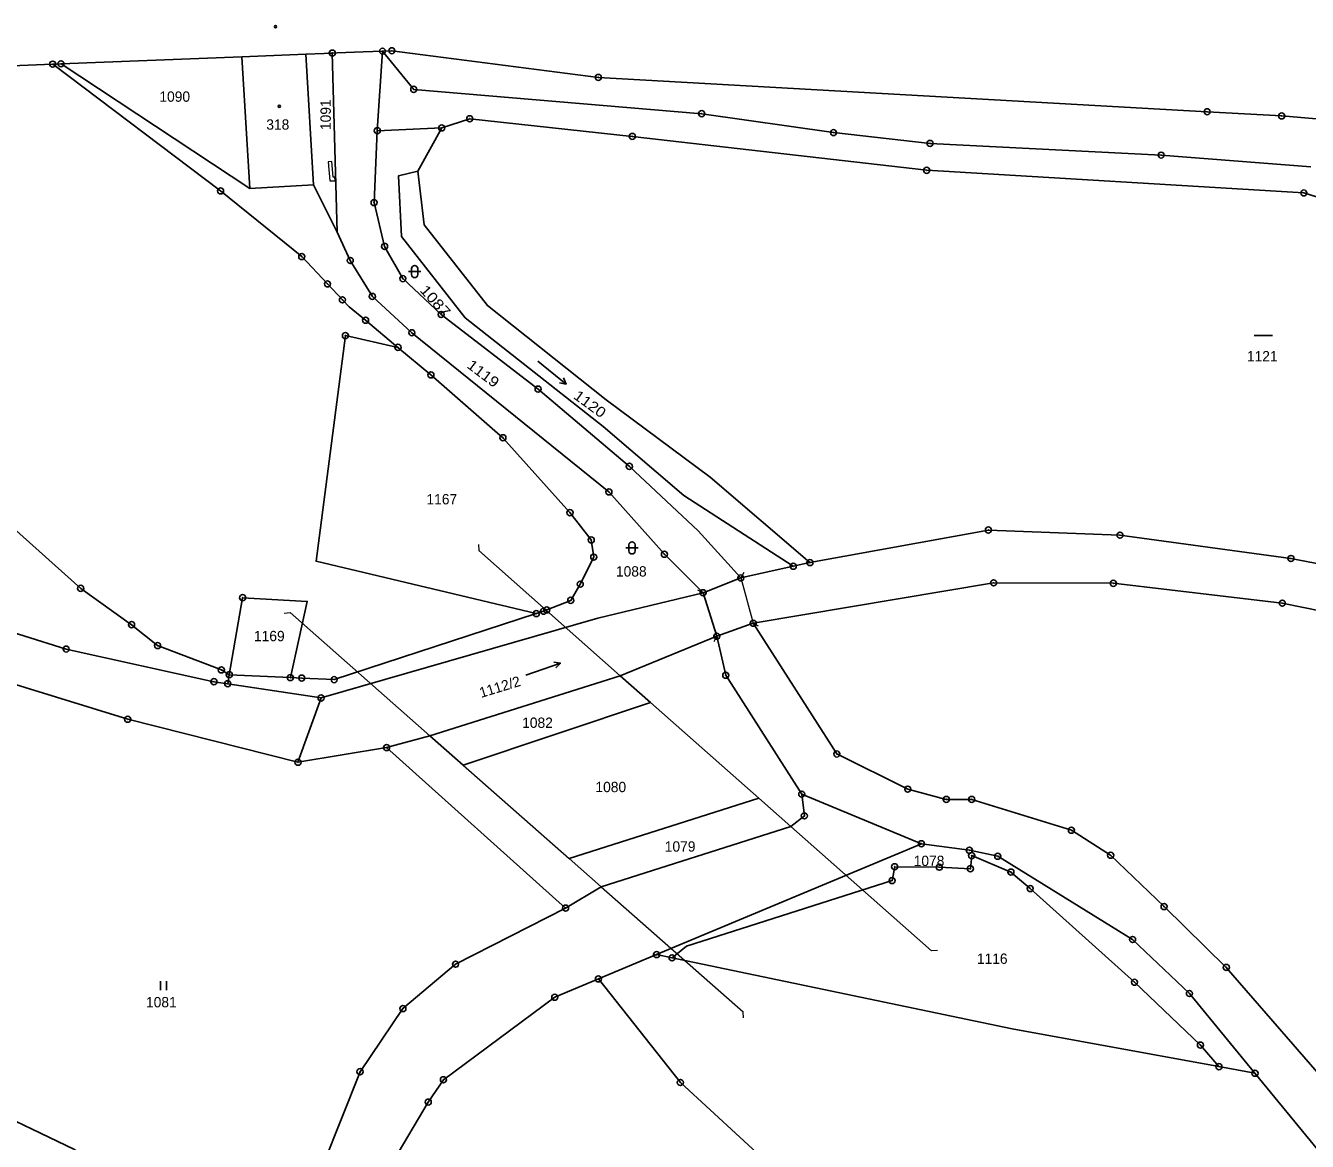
# Model space of a CAD drawing. Extents: x -758887 to -754328, y -1031688 to -1029144.
# Drawn here: x -758435 to -758223.9, y -1029327.6 to -1029143.8 of the extents above; entities that cross this region are included whole.
import ezdxf
from ezdxf.enums import TextEntityAlignment as Align

# ---------------------------------------------------------------- set-up
doc = ezdxf.new("R2010")
doc.units = 0
doc.header["$LTSCALE"] = 0.68
for name, color, linetype, lineweight in [('1', 7, 'Continuous', 25), ('13', 7, 'Continuous', 13), ('3', 7, 'Continuous', 25), ('4', 7, 'Continuous', 13), ('5', 7, 'Continuous', 25), ('8', 7, 'Continuous', 25)]:
    doc.layers.add(name, color=color, linetype=linetype, lineweight=lineweight)
doc.layers.add('2', color=7, linetype='Continuous')

msp = doc.modelspace()

# ---------------------------------------------------------------- linework, layer by layer
at = {"layer": '1'}
for p, q in [((-758429.19, -1029150.13), (-758399.41, -1029148.95)), ((-758399.41, -1029148.95), (-758388.86, -1029148.53)), ((-758388.86, -1029148.53), (-758385.84, -1029148.42)), ((-758387.59, -1029170.04), (-758388.86, -1029148.53)), ((-758385.84, -1029148.42), (-758385.18, -1029148.39)), ((-758385.18, -1029148.39), (-758384.52, -1029148.36)), ((-758384.52, -1029148.36), (-758383.68, -1029148.33)), ((-758383.69, -1029177.86), (-758384.52, -1029148.36)), ((-758377.11, -1029161.14), (-758376.24, -1029148.04)), ((-758376.24, -1029148.04), (-758374.7, -1029147.98)), ((-758430.56, -1029150.18), (-758429.19, -1029150.13)), ((-758398.07, -1029170.69), (-758429.19, -1029150.13)), ((-758383.69, -1029177.86), (-758387.59, -1029170.04)), ((-758308.58, -1029232.9), (-758305.84, -1029232.29)), ((-758323.44, -1029237.26), (-758321.17, -1029244.43)), ((-758315.18, -1029242.29), (-758321.17, -1029244.43)), ((-758321.17, -1029244.43), (-758337.07, -1029250.93)), ((-758391.41, -1029251.24), (-758401.47, -1029250.78)), ((-758337.07, -1029250.93), (-758368.43, -1029260.83)), ((-758337.07, -1029250.93), (-758332.09, -1029255.33)), ((-758390.16, -1029265.19), (-758386.36, -1029254.6)), ((-758368.43, -1029260.83), (-758375.57, -1029262.78)), ((-758375.57, -1029262.78), (-758390.16, -1029265.19)), ((-758307.18, -1029270.45), (-758287.47, -1029278.61)), ((-758331.09, -1029296.88), (-758340.67, -1029300.89))]:
    msp.add_line(p, q, dxfattribs=at)
for points in [[(-758399.41, -1029148.95), (-758398.07, -1029170.69), (-758387.59, -1029170.04)], [(-758383.68, -1029148.33), (-758379.42, -1029148.16), (-758376.24, -1029148.04)], [(-758376.24, -1029148.04), (-758371.09, -1029154.33), (-758323.67, -1029158.34), (-758301.96, -1029161.46), (-758286.05, -1029163.24), (-758247.99, -1029165.17), (-758223.33, -1029167.07)], [(-758374.7, -1029147.98), (-758340.67, -1029152.37), (-758240.41, -1029158.02)], [(-758519.87, -1029156.38), (-758490.37, -1029153.89), (-758473.85, -1029152.5), (-758472.04, -1029152.35), (-758460.36, -1029151.36), (-758456.33, -1029151.2), (-758430.56, -1029150.18)], [(-758430.56, -1029150.18), (-758402.9, -1029171.06), (-758389.54, -1029181.89), (-758385.3, -1029186.39), (-758382.84, -1029189.01), (-758381.73, -1029190.18), (-758379.02, -1029192.38), (-758373.69, -1029196.84)], [(-758240.41, -1029158.02), (-758228.14, -1029158.71), (-758184.57, -1029162.5), (-758098.34, -1029176.6), (-758087.31, -1029177.87)], [(-758116.76, -1029196.06), (-758146.77, -1029190.01), (-758200.54, -1029178.97), (-758224.49, -1029171.39), (-758286.61, -1029167.67), (-758335.09, -1029162.08), (-758361.87, -1029159.17), (-758366.48, -1029160.68)], [(-758377.11, -1029161.14), (-758377.63, -1029172.99), (-758375.9, -1029180.21), (-758372.89, -1029185.52), (-758366.58, -1029191.42), (-758350.62, -1029203.72), (-758335.58, -1029216.44), (-758324.24, -1029227.07), (-758317.22, -1029234.82)], [(-758370.44, -1029167.83), (-758366.48, -1029160.68), (-758377.11, -1029161.14)], [(-758308.58, -1029232.9), (-758326.61, -1029221.24), (-758339.91, -1029209.85), (-758362.61, -1029191.98), (-758373.12, -1029178.58), (-758373.63, -1029168.59), (-758370.44, -1029167.83)], [(-758305.84, -1029232.29), (-758322.28, -1029218.25), (-758339.42, -1029205.48), (-758358.95, -1029189.96), (-758369.35, -1029176.63), (-758370.44, -1029167.83)], [(-758323.44, -1029237.26), (-758329.81, -1029230.93), (-758338.94, -1029220.66), (-758371.41, -1029194.43), (-758377.91, -1029188.45), (-758381.55, -1029182.53), (-758383.69, -1029177.86)], [(-758401.47, -1029250.78), (-758402.78, -1029249.98), (-758413.29, -1029245.97), (-758417.57, -1029242.53), (-758425.95, -1029236.54), (-758437, -1029226.65), (-758467.17, -1029201.22), (-758490.33, -1029182.16)], [(-758821.62, -1029188.2), (-758803.54, -1029192.38), (-758764.19, -1029202.23), (-758728.57, -1029211.45), (-758684.41, -1029222.59), (-758639.98, -1029230.68), (-758608.27, -1029234.2), (-758578.65, -1029235.81), (-758561.56, -1029238.41), (-758526.08, -1029238.52), (-758490.44, -1029236.79), (-758465.04, -1029235.05), (-758428.34, -1029246.54), (-758404, -1029251.92), (-758401.73, -1029252.26)], [(-758373.69, -1029196.84), (-758382.34, -1029194.9), (-758387.19, -1029232.09), (-758350.92, -1029240.7)], [(-758373.69, -1029196.84), (-758368.27, -1029201.38), (-758356.4, -1029211.73), (-758345.36, -1029224.07), (-758341.85, -1029228.57), (-758341.44, -1029231.4), (-758343.67, -1029235.85), (-758345.24, -1029238.52), (-758349.18, -1029240.09), (-758349.72, -1029240.31), (-758350.92, -1029240.7)], [(-758305.84, -1029232.29), (-758276.44, -1029226.93), (-758254.79, -1029227.78), (-758226.62, -1029231.62), (-758183.35, -1029239.91), (-758120.85, -1029256.32)], [(-758323.44, -1029237.26), (-758317.22, -1029234.82), (-758308.58, -1029232.9)], [(-757986.46, -1029302.93), (-758014.95, -1029292.13), (-758063.96, -1029279.67), (-758122.9, -1029264.06), (-758185.39, -1029247.65), (-758228.04, -1029238.98), (-758255.87, -1029235.71), (-758275.59, -1029235.63), (-758315.18, -1029242.29)], [(-758401.47, -1029250.78), (-758399.28, -1029238.08), (-758388.64, -1029238.69), (-758391.41, -1029251.24)], [(-758386.36, -1029254.6), (-758340.79, -1029241.46), (-758323.44, -1029237.26)], [(-758350.92, -1029240.7), (-758384.2, -1029251.58), (-758389.53, -1029251.33), (-758391.41, -1029251.24)], [(-758214.63, -1029325.07), (-758237.26, -1029298.99), (-758247.51, -1029288.97), (-758256.31, -1029280.52), (-758262.77, -1029276.4), (-758279.18, -1029271.31), (-758283.38, -1029271.32), (-758289.72, -1029269.62), (-758301.41, -1029263.83), (-758315.18, -1029242.29)], [(-758307.18, -1029270.45), (-758319.71, -1029250.86), (-758321.17, -1029244.43)], [(-758390.16, -1029265.19), (-758418.21, -1029258.11), (-758446.92, -1029249.26), (-758453.37, -1029246.98)], [(-758401.47, -1029250.78), (-758401.73, -1029252.26), (-758386.36, -1029254.6)], [(-758332.09, -1029255.33), (-758362.95, -1029265.65), (-758368.43, -1029260.83)], [(-758375.57, -1029262.78), (-758346.08, -1029289.22), (-758340.22, -1029285.69)], [(-758309.01, -1029275.75), (-758306.76, -1029274.02), (-758307.18, -1029270.45)], [(-758287.47, -1029278.61), (-758331.09, -1029296.88), (-758328.55, -1029297.41)], [(-758232.54, -1029316.42), (-758243.34, -1029303.29), (-758252.7, -1029294.39), (-758274.91, -1029280.68), (-758279.57, -1029279.69), (-758287.47, -1029278.61)], [(-758328.55, -1029297.41), (-758326.19, -1029295.49), (-758292.3, -1029284.68), (-758291.88, -1029282.41), (-758284.54, -1029282.48), (-758279.41, -1029282.73), (-758279.2, -1029280.56), (-758272.73, -1029283.29), (-758269.56, -1029286.01), (-758252.38, -1029301.44), (-758241.53, -1029311.79), (-758238.47, -1029315.34), (-758232.54, -1029316.42)], [(-758392.05, -1029348.07), (-758389, -1029338.93), (-758379.94, -1029316.17), (-758372.88, -1029305.78), (-758364.21, -1029298.46), (-758346.08, -1029289.22)], [(-758238.47, -1029315.34), (-758272.52, -1029309.13), (-758328.55, -1029297.41)], [(-758340.67, -1029300.89), (-758347.87, -1029303.9), (-758366.2, -1029317.5), (-758368.71, -1029321.17), (-758374.39, -1029330.73), (-758378.89, -1029344.86), (-758384.41, -1029360.14), (-758394.64, -1029390.44), (-758399.55, -1029401.61), (-758407.78, -1029412.68), (-758420.82, -1029419.96), (-758434.38, -1029424.1)], [(-758190.92, -1029431.64), (-758198.56, -1029424.31), (-758240.61, -1029385.61), (-758265.6, -1029364.46), (-758297.96, -1029342.37), (-758312.48, -1029331.46), (-758327.18, -1029317.95), (-758340.67, -1029300.89)], [(-758454.59, -1029315.76), (-758427.08, -1029328.92), (-758412.67, -1029338.97), (-758404.39, -1029347.29), (-758392.05, -1029348.07)], [(-758132.9, -1029435.24), (-758143.97, -1029427.02), (-758147.78, -1029422.95), (-758152.98, -1029416.21), (-758166.32, -1029397.91), (-758201.41, -1029354.28), (-758232.54, -1029316.42)]]:
    msp.add_lwpolyline(points, dxfattribs=at)
msp.add_lwpolyline([(-758340.22, -1029285.69), (-758309.01, -1029275.75), (-758314.23, -1029271.13), (-758345.49, -1029281.04)], close=True, dxfattribs=at)
at = {"layer": '13'}
msp.add_lwpolyline([(-758384.06, -1029169.39), (-758384.07, -1029168.79), (-758384.37, -1029168.79), (-758384.61, -1029166.21), (-758385.21, -1029166.27), (-758384.91, -1029169.39)], close=True, dxfattribs=at)
at = {"layer": '3'}
for p, q in [((-758371.941, -1029184.351), (-758369.939, -1029184.351)), ((-758371.441, -1029183.851), (-758371.441, -1029184.852)), ((-758370.439, -1029184.852), (-758370.439, -1029183.851)), ((-758232.668, -1029194.86), (-758229.668, -1029194.86)), ((-758345.991, -1029202.885), (-758347.066, -1029202.66)), ((-758336.141, -1029229.871), (-758334.139, -1029229.871)), ((-758335.641, -1029229.371), (-758335.641, -1029230.372)), ((-758334.639, -1029230.372), (-758334.639, -1029229.371)), ((-758346.934, -1029248.866), (-758347.695, -1029249.658)), ((-758412.801, -1029302.75), (-758412.801, -1029301.25)), ((-758411.8, -1029302.75), (-758411.8, -1029301.25))]:
    msp.add_line(p, q, dxfattribs=at)
for points in [[(-758350.654, -1029199.109), (-758345.991, -1029202.885), (-758346.434, -1029201.881)], [(-758352.608, -1029250.819), (-758346.934, -1029248.866), (-758348.022, -1029248.71)]]:
    msp.add_lwpolyline(points, dxfattribs=at)
for centre, start, end in [((-758370.94, -1029183.8509), 0, 180), ((-758370.94, -1029184.8509), 180, 359.98789), ((-758335.14, -1029229.3709), 0, 180), ((-758335.14, -1029230.3709), 180, 359.98789)]:
    msp.add_arc(centre, 0.5, start, end, dxfattribs=at)
at = {"layer": '4'}
for p, q in [((-758360.442, -1029229.301), (-758360.389, -1029230.299)), ((-758360.39, -1029230.3), (-758337.07, -1029250.93)), ((-758316.719, -1029233.954), (-758317.219, -1029234.82)), ((-758317.22, -1029234.82), (-758315.18, -1029242.29)), ((-758324.331, -1029236.805), (-758323.44, -1029237.259)), ((-758392.448, -1029240.609), (-758391.451, -1029240.539)), ((-758391.45, -1029240.54), (-758368.43, -1029260.83)), ((-758314.314, -1029242.791), (-758315.18, -1029242.291)), ((-758321.625, -1029245.321), (-758321.171, -1029244.43)), ((-758332.09, -1029255.33), (-758314.23, -1029271.13)), ((-758362.95, -1029265.65), (-758345.49, -1029281.04)), ((-758309.01, -1029275.75), (-758285.83, -1029296.25)), ((-758340.22, -1029285.69), (-758316.84, -1029306.29)), ((-758284.831, -1029296.198), (-758285.829, -1029296.251)), ((-758316.771, -1029307.288), (-758316.841, -1029306.291))]:
    msp.add_line(p, q, dxfattribs=at)
at = {"layer": '5'}
for centre in [(-758393.8568, -1029144.0092), (-758393.2368, -1029157.1392)]:
    msp.add_circle(centre, 0.175, dxfattribs=at)
at = {"layer": '8'}
for centre, radius in [((-758384.52, -1029148.3599), 0.5), ((-758376.24, -1029148.0399), 0.5), ((-758374.7, -1029147.9799), 0.5), ((-758430.56, -1029150.1799), 0.5), ((-758429.19, -1029150.1299), 0.5), ((-758384.52, -1029148.3599), 0.0303), ((-758376.24, -1029148.0399), 0.0303), ((-758374.7, -1029147.9799), 0.0303), ((-758430.56, -1029150.1799), 0.0303), ((-758429.19, -1029150.1299), 0.0303), ((-758340.67, -1029152.3699), 0.5), ((-758371.09, -1029154.3299), 0.5), ((-758340.67, -1029152.3699), 0.0303), ((-758371.09, -1029154.3299), 0.0303), ((-758323.67, -1029158.3399), 0.5), ((-758323.67, -1029158.3399), 0.0303), ((-758240.41, -1029158.0199), 0.5), ((-758240.41, -1029158.0199), 0.0303), ((-758228.14, -1029158.7099), 0.5), ((-758366.48, -1029160.6799), 0.5), ((-758361.87, -1029159.1699), 0.5), ((-758361.87, -1029159.1699), 0.0303), ((-758228.14, -1029158.7099), 0.0303), ((-758377.11, -1029161.1399), 0.5), ((-758377.11, -1029161.1399), 0.0303), ((-758366.48, -1029160.6799), 0.0303), ((-758335.09, -1029162.0799), 0.5), ((-758335.09, -1029162.0799), 0.0303), ((-758301.96, -1029161.4599), 0.5), ((-758301.96, -1029161.4599), 0.0303), ((-758286.05, -1029163.2399), 0.5), ((-758286.05, -1029163.2399), 0.0303), ((-758247.99, -1029165.1699), 0.5), ((-758247.99, -1029165.1699), 0.0303), ((-758286.61, -1029167.6699), 0.5), ((-758286.61, -1029167.6699), 0.0303), ((-758402.9, -1029171.0599), 0.5), ((-758402.9, -1029171.0599), 0.0303), ((-758224.49, -1029171.3899), 0.5), ((-758377.63, -1029172.9899), 0.5), ((-758377.63, -1029172.9899), 0.0303), ((-758224.49, -1029171.3899), 0.0303), ((-758389.54, -1029181.8899), 0.5), ((-758375.9, -1029180.2099), 0.5), ((-758375.9, -1029180.2099), 0.0303), ((-758389.54, -1029181.8899), 0.0303), ((-758381.55, -1029182.5299), 0.5), ((-758381.55, -1029182.5299), 0.0303), ((-758385.3, -1029186.3899), 0.5), ((-758372.89, -1029185.5199), 0.5), ((-758372.89, -1029185.5199), 0.0303), ((-758385.3, -1029186.3899), 0.0303), ((-758377.91, -1029188.4499), 0.5), ((-758382.84, -1029189.0099), 0.5), ((-758382.84, -1029189.0099), 0.0303), ((-758377.91, -1029188.4499), 0.0303), ((-758379.02, -1029192.3799), 0.5), ((-758366.58, -1029191.4199), 0.5), ((-758366.58, -1029191.4199), 0.0303), ((-758379.02, -1029192.3799), 0.0303), ((-758371.41, -1029194.4299), 0.5), ((-758382.34, -1029194.8999), 0.5), ((-758382.34, -1029194.8999), 0.0303), ((-758373.69, -1029196.8399), 0.5), ((-758371.41, -1029194.4299), 0.0303), ((-758373.69, -1029196.8399), 0.0303), ((-758368.27, -1029201.3799), 0.5), ((-758368.27, -1029201.3799), 0.0303), ((-758350.62, -1029203.7199), 0.5), ((-758350.62, -1029203.7199), 0.0303), ((-758356.4, -1029211.7299), 0.5), ((-758356.4, -1029211.7299), 0.0303), ((-758335.58, -1029216.4399), 0.5), ((-758335.58, -1029216.4399), 0.0303), ((-758338.94, -1029220.6599), 0.5), ((-758338.94, -1029220.6599), 0.0303), ((-758345.36, -1029224.0699), 0.5), ((-758345.36, -1029224.0699), 0.0303), ((-758341.85, -1029228.5699), 0.5), ((-758276.44, -1029226.9299), 0.5), ((-758276.44, -1029226.9299), 0.0303), ((-758254.79, -1029227.7799), 0.5), ((-758254.79, -1029227.7799), 0.0303), ((-758341.85, -1029228.5699), 0.0303), ((-758341.44, -1029231.3999), 0.5), ((-758341.44, -1029231.3999), 0.0303), ((-758329.81, -1029230.9299), 0.5), ((-758329.81, -1029230.9299), 0.0303), ((-758305.84, -1029232.2899), 0.5), ((-758305.84, -1029232.2899), 0.0303), ((-758226.62, -1029231.6199), 0.5), ((-758226.62, -1029231.6199), 0.0303), ((-758317.22, -1029234.8199), 0.5), ((-758308.58, -1029232.8999), 0.5), ((-758308.58, -1029232.8999), 0.0303), ((-758425.95, -1029236.5399), 0.5), ((-758425.95, -1029236.5399), 0.0303), ((-758343.67, -1029235.8499), 0.5), ((-758343.67, -1029235.8499), 0.0303), ((-758317.22, -1029234.8199), 0.0303), ((-758275.59, -1029235.6299), 0.5), ((-758275.59, -1029235.6299), 0.0303), ((-758255.87, -1029235.7099), 0.5), ((-758255.87, -1029235.7099), 0.0303), ((-758399.28, -1029238.0799), 0.5), ((-758399.28, -1029238.0799), 0.0303), ((-758345.24, -1029238.5199), 0.5), ((-758345.24, -1029238.5199), 0.0303), ((-758323.44, -1029237.2599), 0.5), ((-758323.44, -1029237.2599), 0.0303), ((-758228.04, -1029238.9799), 0.5), ((-758350.92, -1029240.6999), 0.5), ((-758350.92, -1029240.6999), 0.0303), ((-758349.72, -1029240.3099), 0.5), ((-758349.72, -1029240.3099), 0.0303), ((-758349.18, -1029240.0899), 0.5), ((-758349.18, -1029240.0899), 0.0303), ((-758228.04, -1029238.9799), 0.0303), ((-758417.57, -1029242.5299), 0.5), ((-758417.57, -1029242.5299), 0.0303), ((-758315.18, -1029242.2899), 0.5), ((-758315.18, -1029242.2899), 0.0303), ((-758321.17, -1029244.4299), 0.5), ((-758321.17, -1029244.4299), 0.0303), ((-758428.34, -1029246.5399), 0.5), ((-758428.34, -1029246.5399), 0.0303), ((-758413.29, -1029245.9699), 0.5), ((-758413.29, -1029245.9699), 0.0303), ((-758402.78, -1029249.9799), 0.5), ((-758402.78, -1029249.9799), 0.0303), ((-758401.47, -1029250.7799), 0.5), ((-758401.47, -1029250.7799), 0.0303), ((-758391.41, -1029251.2399), 0.5), ((-758391.41, -1029251.2399), 0.0303), ((-758389.53, -1029251.3299), 0.5), ((-758389.53, -1029251.3299), 0.0303), ((-758384.2, -1029251.5799), 0.5), ((-758319.71, -1029250.8599), 0.5), ((-758319.71, -1029250.8599), 0.0303), ((-758404, -1029251.9199), 0.5), ((-758404, -1029251.9199), 0.0303), ((-758401.73, -1029252.2599), 0.5), ((-758401.73, -1029252.2599), 0.0303), ((-758384.2, -1029251.5799), 0.0303), ((-758386.36, -1029254.5999), 0.5), ((-758386.36, -1029254.5999), 0.0303), ((-758418.21, -1029258.1099), 0.5), ((-758418.21, -1029258.1099), 0.0303), ((-758375.57, -1029262.7799), 0.5), ((-758375.57, -1029262.7799), 0.0303), ((-758301.41, -1029263.8299), 0.5), ((-758301.41, -1029263.8299), 0.0303), ((-758390.16, -1029265.1899), 0.5), ((-758390.16, -1029265.1899), 0.0303), ((-758307.18, -1029270.4499), 0.5), ((-758289.72, -1029269.6199), 0.5), ((-758289.72, -1029269.6199), 0.0303), ((-758307.18, -1029270.4499), 0.0303), ((-758283.38, -1029271.3199), 0.5), ((-758283.38, -1029271.3199), 0.0303), ((-758279.18, -1029271.3099), 0.5), ((-758279.18, -1029271.3099), 0.0303), ((-758306.76, -1029274.0199), 0.5), ((-758306.76, -1029274.0199), 0.0303), ((-758262.77, -1029276.3999), 0.5), ((-758262.77, -1029276.3999), 0.0303), ((-758287.47, -1029278.6099), 0.5), ((-758287.47, -1029278.6099), 0.0303), ((-758279.57, -1029279.6899), 0.5), ((-758279.2, -1029280.5599), 0.5), ((-758279.57, -1029279.6899), 0.0303), ((-758279.2, -1029280.5599), 0.0303), ((-758274.91, -1029280.6799), 0.5), ((-758274.91, -1029280.6799), 0.0303), ((-758256.31, -1029280.5199), 0.5), ((-758256.31, -1029280.5199), 0.0303), ((-758291.88, -1029282.4099), 0.5), ((-758291.88, -1029282.4099), 0.0303), ((-758284.54, -1029282.4799), 0.5), ((-758284.54, -1029282.4799), 0.0303), ((-758279.41, -1029282.7299), 0.5), ((-758279.41, -1029282.7299), 0.0303), ((-758272.73, -1029283.2899), 0.5), ((-758292.3, -1029284.6799), 0.5), ((-758292.3, -1029284.6799), 0.0303), ((-758272.73, -1029283.2899), 0.0303), ((-758269.56, -1029286.0099), 0.5), ((-758269.56, -1029286.0099), 0.0303), ((-758346.08, -1029289.2199), 0.5), ((-758346.08, -1029289.2199), 0.0303), ((-758247.51, -1029288.9699), 0.5), ((-758247.51, -1029288.9699), 0.0303), ((-758252.7, -1029294.3899), 0.5), ((-758252.7, -1029294.3899), 0.0303), ((-758331.09, -1029296.8799), 0.5), ((-758331.09, -1029296.8799), 0.0303), ((-758328.55, -1029297.4099), 0.5), ((-758328.55, -1029297.4099), 0.0303), ((-758364.21, -1029298.4599), 0.5), ((-758364.21, -1029298.4599), 0.0303), ((-758237.26, -1029298.9899), 0.5), ((-758237.26, -1029298.9899), 0.0303), ((-758340.67, -1029300.8899), 0.5), ((-758340.67, -1029300.8899), 0.0303), ((-758252.38, -1029301.4399), 0.5), ((-758252.38, -1029301.4399), 0.0303), ((-758347.87, -1029303.8999), 0.5), ((-758347.87, -1029303.8999), 0.0303), ((-758243.34, -1029303.2899), 0.5), ((-758243.34, -1029303.2899), 0.0303), ((-758372.88, -1029305.7799), 0.5), ((-758372.88, -1029305.7799), 0.0303), ((-758241.53, -1029311.7899), 0.5), ((-758241.53, -1029311.7899), 0.0303), ((-758379.94, -1029316.1699), 0.5), ((-758379.94, -1029316.1699), 0.0303), ((-758238.47, -1029315.3399), 0.5), ((-758238.47, -1029315.3399), 0.0303), ((-758232.54, -1029316.4199), 0.5), ((-758232.54, -1029316.4199), 0.0303), ((-758366.2, -1029317.4999), 0.5), ((-758366.2, -1029317.4999), 0.0303), ((-758327.18, -1029317.9499), 0.5), ((-758327.18, -1029317.9499), 0.0303), ((-758368.71, -1029321.1699), 0.5), ((-758368.71, -1029321.1699), 0.0303)]:
    msp.add_circle(centre, radius, dxfattribs=at)

# ---------------------------------------------------------------- texts
at = {"layer": '2'}
for s, p in [('1090', (-758410.46, -1029156.376)), ('318', (-758393.479, -1029160.976)), ('1121', (-758231.34, -1029199.146)), ('1167', (-758366.47, -1029222.706)), ('1088', (-758335.26, -1029234.596)), ('1169', (-758394.88, -1029245.246)), ('1082', (-758350.71, -1029259.526)), ('1080', (-758338.64, -1029270.116)), ('1079', (-758327.22, -1029279.916)), ('1078', (-758286.22, -1029282.286)), ('1116', (-758275.82, -1029298.406)), ('1081', (-758412.66, -1029305.566))]:
    msp.add_text(s, height=1.7, dxfattribs=at).set_placement(p, align=Align.CENTER)
for s, rotation, p in [('1091', 90, (-758384.753, -1029158.51)), ('1112/2', 17, (-758356.665, -1029253.5818))]:
    msp.add_text(s, height=1.7, rotation=rotation, dxfattribs=at).set_placement(p, align=Align.CENTER)
for s, rotation, width, p in [('1087', 312, 1.2, (-758368.1711, -1029189.7562)), ('1119', 323, 1.15, (-758360.1605, -1029201.8279)), ('1120', 324, 1.15, (-758342.5796, -1029206.8576))]:
    msp.add_text(s, height=1.7, rotation=rotation, dxfattribs=dict(at, width=width)).set_placement(p, align=Align.CENTER)

doc.saveas('drawing.dxf')
